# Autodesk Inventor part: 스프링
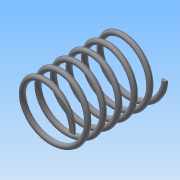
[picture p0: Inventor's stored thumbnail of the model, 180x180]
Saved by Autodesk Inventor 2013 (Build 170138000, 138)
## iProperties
Created: 2018-06
Part Number: 스프링
Material: 일반
Document SubType Name: Modeling
Designer: Administrator
Density: 1 g/cm^3
Mass: -0.137845 g
Surface Area: 106.475 cm^2
Volume: -0.137845 cm^3
Author: Administrator
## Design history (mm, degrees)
sketch "스케치1"
  geometry: L1 (0, 0)-(0, 73.25); L2 (0, 0)-(22.5, 0); L3 (0, 73.25)-(22.5, 73.25); C1 r 2 at (22.5, 0)
  constraints: 6 end point, 1 centre point, 1 coincident, 1 perpendicular, 1 vertical
  dimensions: "d0" = 73.25 distance of L1.start L1.end (derived); "d1" = 22.5 distance of L1.start L2.end; "d2" = 4 diameter of C1; "d3" = 22.5 distance of L1.end L3.end
feature "코일1" sketch "스케치1" pitch "d4" = 10; turns "d6" = 6; dims "d5" = 73.25 (= d0), "d7" = 0, angle "d8" = 90 deg, angle "d9" = 90 deg, "d10" = 0, "d11" = 0
sketch "스케치2"
  geometry: L1 (73.25, 25)-(0, 25); L2 (0, 25)-(0, -25); L3 (0, -25)-(73.25, -25); L4 (73.25, -25)-(73.25, 25); 2 further points
  constraints: 8 end point, 2 parallel, 1 coincident, 1 horizontal, 1 midpoint, 1 perpendicular
  dimensions: "d12" = 73.25 distance of L2.end L3.end (derived); "d14" = 50 distance of L3.end L1.start
extrude "돌출1" sketch "스케치2" stored distance "d15" = 10; taper "d16" = 0 deg
node "솔리드1"
